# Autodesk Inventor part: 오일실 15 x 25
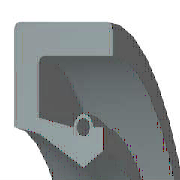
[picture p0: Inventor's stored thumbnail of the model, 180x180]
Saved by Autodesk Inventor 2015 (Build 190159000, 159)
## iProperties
IsCustomPart: 0
Created: 2015-10
Part Number: 오일실 15 x 25
Material: 고무
Description: 오일-실
Document SubType Name: Modeling
Standard: KS B 2804
Designer: mdu
Standards Organization: KS
Language: ko-KR
Size Designation: S - 15 25 7
Categories: <MemberInstance><Categories><Category DisplayName="샤프트 부품" InternalName="7f7aeb1f-a693-4053-b835-cee3144e0d98" Mnemonic="SHFT"><Category DisplayName="실링" Intern
Density: 0.93 g/cm^3
Appearance: 고무 - 검은색 - 버전 1.1
Author: mdu
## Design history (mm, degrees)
revolve "본체" stored, may be unused: angle "d17" = 90 deg
revolve "스프링1" stored, may be unused: angle "d18" = 90 deg
body "Solid1"
sketch "스케치1"
  geometry: L1 (0, 12.5)-(7, 12.5); L2 (7, 12.5)-(7, 11.25); L3 (7, 11.25)-(1.75, 11.25); L4 (0, 12.5)-(0, 9.6); L5 (0, 9.6)-(1.75, 9.25); L6 (1.75, 9.25)-(4.9, 7.5); L7 (4.9, 7.5)-(0, 7.5); L8 (6.3, 8.375)-(6.3, 9.6); L9 (0, 0)-(9.586, 0) reference; L10 (4.9, 7.5)-(6.3, 8.375); L11 (0, 18)-(0, -3) reference; L12 (-1.917, 0)-(11.503, 0) reference; L13 (4.2, 9.6)-(1.75, 10.09); L14 (1.75, 10.09)-(1.75, 11.25); L15 (6.3, 9.6)-(5.6, 9.6); C1 r 0.455 at (4.9, 9.6); A1 r 0.7 centre (4.9, 9.6) between (5.6, 9.6) and (4.2, 9.6)
  constraints: 26 end point, 5 horizontal alignment, 4 perpendicular, 2 centre point, 2 collinear, 2 horizontal, 2 parallel, 2 point on circle, 2 point on line, 2 vertical alignment, 1 coincident
  dimensions: "d0" = 25 diameter of L1 L9 (= SD2); "d1" = 16.75 diameter of L8.start L9 (= ABDM); "d2" = 1.25 distance of L1.end L2.end (computed from SD); "d3" = 0.91 diameter of C1 (= SPDI); "d4" = 1.4 diameter of A1 (= SPDA); "d5" = 15 diameter of L6.end L9 (= NND); "d6" = 18.5 diameter of L5.end L9 (= TKDM); "d7" = 19.2 diameter of L4.end L9 (= HLDM); "d8" = 4.9 distance from line of C1.centre L4 (= SPDST); "d9" = 6.3 distance between parallel lines of L8 L4 (= SDI); "d10" = 7 distance between parallel lines of L2 L4 (= SWDT); "d12" = 1.75 distance between parallel lines of L14 L4 (= SD)
fillet "모깎기1" dims "d11" = 0.3 (= RR)
other parameters: "SD2" = 25 [user parameter; used in 1 equation term], "SWDT" = 7 [user parameter; used in 1 equation term], "RR" = 0.3 [user parameter; used in 1 equation term], "SD" = 1.75 [user parameter; used in 2 equation terms], "NND" = 15 [user parameter; used in 1 equation term], "SPDA" = 1.4 [user parameter; used in 1 equation term], "SPDI" = 0.91 [user parameter; used in 1 equation term], "TKDM" = 18.5 [user parameter; used in 1 equation term], "HLDM" = 19.2 [user parameter; used in 1 equation term], "ABDM" = 16.75 [user parameter; used in 1 equation term], "SDI" = 6.3 [user parameter; used in 1 equation term], "SPDST" = 4.9 [user parameter; used in 1 equation term], "d13" = 0, "d14" = 0, "d15" = 0, "LAB" = 0.35 [user parameter]
